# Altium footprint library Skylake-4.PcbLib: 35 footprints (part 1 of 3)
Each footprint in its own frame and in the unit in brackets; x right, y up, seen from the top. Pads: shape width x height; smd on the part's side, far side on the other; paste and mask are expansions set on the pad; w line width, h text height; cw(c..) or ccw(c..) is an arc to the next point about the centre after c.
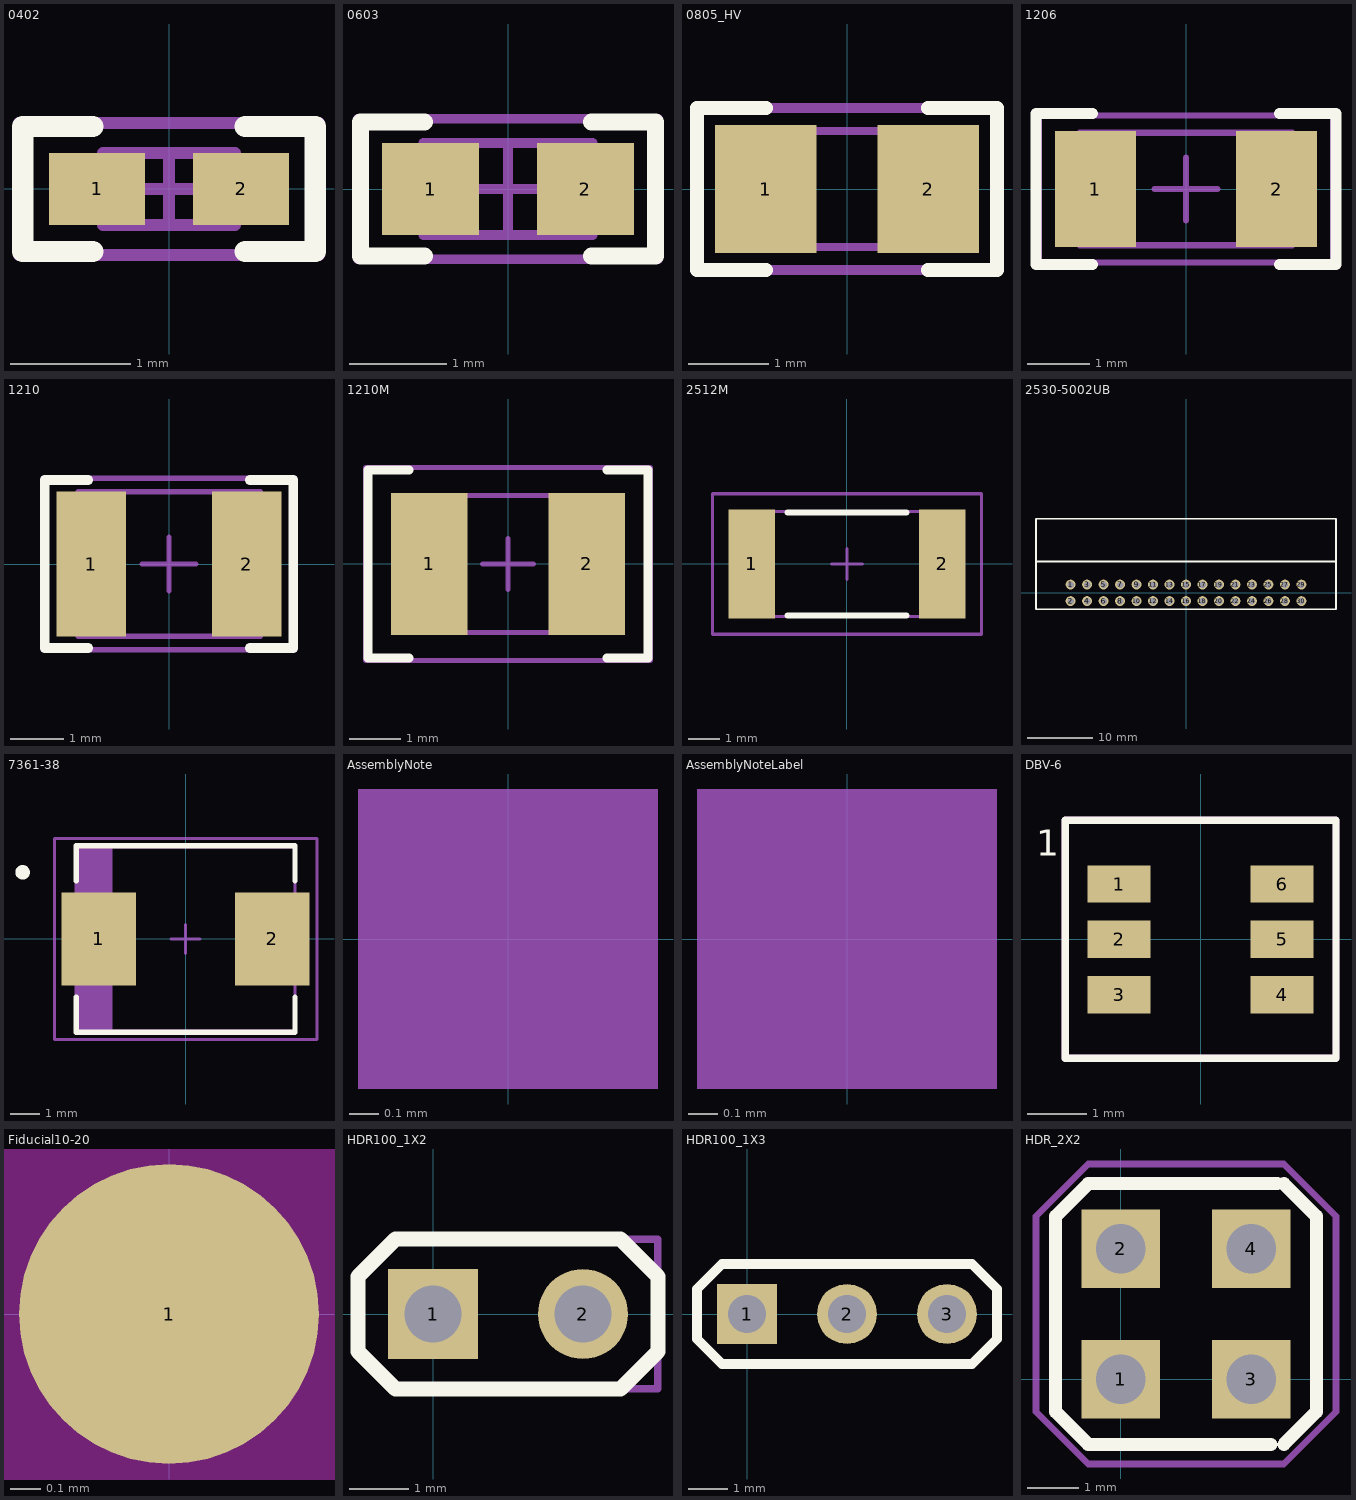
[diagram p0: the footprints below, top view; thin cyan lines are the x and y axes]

## 0402 [mm] "0402 from SM-752 data"
height 0.6
pads (2):
  rect 0.8x0.6 smd: 1(-0.6,0) 2(0.6,0)
Top Overlay:
  lines w0.178: -0.635,-0.521 -1.219,-0.521 -1.219,0.521 -0.635,0.521 ; 0.635,-0.521 1.219,-0.521 1.219,0.521 0.635,0.521
Mechanical 5:
  lines w0.1: -1.25,-0.55 -1.25,0.55 1.25,0.55 1.25,-0.55 -1.25,-0.55
  text ".Designator" at 0.585,0.274 h0.76
Mechanical 13:
  lines w0.1: -0.35,-0.3 -0.35,0.3 ; 0.35,-0.3 0.35,0.3 ; -0.55,-0.3 0.55,-0.3 0.55,0.3 -0.55,0.3 -0.55,-0.3
Mechanical 15:
  lines w0.1: -0.3,0 0.3,0 ; 0,-0.3 0,0.3 ; -1.25,-0.55 1.25,-0.55 1.25,0.55 -1.25,0.55 -1.25,-0.55
3D body: height 0.6, standoff 0, extent 0.351,-0.299 0.549,0.299
3D body: height 0.6, standoff 0, extent -0.349,-0.299 0.349,0.299
3D body: height 0.6, standoff 0, extent -0.549,-0.299 -0.351,0.299

## 0603 [mm] "0603 from SM-752 data"
height 0.85
pads (2):
  rect 1x0.95 smd: 1(-0.8,0) 2(0.8,0)
Top Overlay:
  lines w0.178: -0.864,-0.691 -1.524,-0.691 -1.524,0.693 -0.864,0.693 ; 0.864,-0.691 1.524,-0.691 1.524,0.693 0.864,0.693
Mechanical 5:
  lines w0.1: -1.55,-0.725 -1.55,0.725 1.55,0.725 1.55,-0.725 -1.55,-0.725
  text ".Designator" at -0.583,-0.298 h0.76
Mechanical 13:
  lines w0.1: -0.55,-0.475 -0.55,0.475 ; 0.55,-0.475 0.55,0.475 ; -0.875,-0.475 0.875,-0.475 0.875,0.475 -0.875,0.475 -0.875,-0.475
Mechanical 15:
  lines w0.1: -0.475,0 0.475,0 ; 0,-0.475 0,0.475 ; -1.55,-0.725 1.55,-0.725 1.55,0.725 -1.55,0.725 -1.55,-0.725
3D body: height 0.85, standoff 0, extent -0.874,-0.474 -0.551,0.474
3D body: height 0.85, standoff 0, extent -0.549,-0.474 0.549,0.474
3D body: height 0.85, standoff 0, extent 0.551,-0.474 0.874,0.474

## 0805_HV [mil] "0805 with 30mil clearance between pads"
height 43.31
pads (2):
  rect 50x63 smd: 1(-40,0) 2(40,0)
Top Overlay:
  lines w7: -40,-40 -74,-40 -74,0 -74,40 -40,40 ; 40,-40 74,-40 74,0 74,40 40,40
Mechanical 5:
  lines w5: -74,-40 -74,40 74,40 74,-40 -74,-40
  text ".Designator" at -21.12,-11.04 h30
Mechanical 13:
  lines w3.94: -25.59,-28.54 -25.59,28.54 ; 25.59,-28.54 25.59,28.54 ; -43.31,-28.54 43.31,-28.54 43.31,28.54 -43.31,28.54 -43.31,-28.54
3D body: height 43.31, standoff 0, extent -43.29,-28.52 -25.61,28.52
3D body: height 43.31, standoff 0, extent -25.57,-28.52 25.57,28.52
3D body: height 43.31, standoff 0, extent 25.61,-28.52 43.29,28.52

## 1206 [mm] "1206 from SM-752 data"
height 1.35
pads (2):
  rect 1.3x1.85 smd: 1(-1.45,0) 2(1.45,0)
Top Overlay:
  lines w0.178: -1.5,-1.21 -2.4,-1.21 -2.4,1.21 -1.5,1.21 ; 1.5,-1.21 2.4,-1.21 2.4,1.21 1.5,1.21
Mechanical 5:
  lines w0.1: -1.7,-0.9 -1.7,0.9 1.7,0.9 1.7,-0.9 -1.7,-0.9
  text ".Designator" at 0.404,0.15 h0.81
Mechanical 13:
  lines w0.1: -1.2,-0.9 -1.2,0.9 ; 1.2,-0.9 1.2,0.9 ; -1.7,-0.9 -1.7,0.9 1.7,0.9 1.7,-0.9 -1.7,-0.9
Mechanical 15:
  lines w0.1: -0.5,0 0.5,0 ; 0,-0.5 0,0.5 ; -2.35,-1.175 -2.35,1.175 2.35,1.175 2.35,-1.175 -2.35,-1.175
3D body: height 1.35, standoff 0, extent 1.201,-0.899 1.699,0.899
3D body: height 1.35, standoff 0, extent -1.199,-0.899 1.199,0.899
3D body: height 1.35, standoff 0, extent -1.699,-0.899 -1.201,0.899

## 1210 [mm] "1210 from SM-752 data"
height 1.35
pads (2):
  rect 1.3x2.7 smd: 1(-1.45,0) 2(1.45,0)
Top Overlay:
  lines w0.178: -1.511,-1.568 -2.316,-1.568 -2.316,1.568 -1.511,1.568 ; 1.511,-1.568 2.316,-1.568 2.316,1.568 1.511,1.568
Mechanical 5:
  lines w0.1: -1.7,-1.35 1.7,-1.35 1.7,1.35 -1.7,1.35 -1.7,-1.35
  text ".Designator" at 0.307,0.066 h0.76
Mechanical 13:
  lines w0.1: -1.2,-1.35 -1.2,1.35 ; 1.2,-1.35 1.2,1.35 ; -1.7,-1.35 -1.7,1.35 1.7,1.35 1.7,-1.35 -1.7,-1.35
Mechanical 15:
  lines w0.1: -0.5,0 0.5,0 ; 0,-0.5 0,0.5 ; -2.35,-1.6 -2.35,1.6 2.35,1.6 2.35,-1.6 -2.35,-1.6
3D body: height 1.35, standoff 0, extent -1.699,-1.349 -1.201,1.349
3D body: height 1.35, standoff 0, extent -1.199,-1.349 1.199,1.349
3D body: height 1.35, standoff 0, extent 1.201,-1.349 1.699,1.349

## 1210M [mm] "1210 from SM-752 data"
height 1.35
pads (2):
  rect 1.5x2.8 smd: 1(-1.55,0) 2(1.55,0)
Top Overlay:
  lines w0.178: -1.95,-1.85 -2.75,-1.85 -2.75,1.85 -1.95,1.85 ; 1.95,-1.85 2.75,-1.85 2.75,1.85 1.95,1.85
Mechanical 5:
  lines w0.1: -1.7,-1.35 -1.7,1.35 1.7,1.35 1.7,-1.35 -1.7,-1.35
  text ".Designator" at 0.58,0.169 h0.76
Mechanical 13:
  lines w0.1: -1.2,-1.35 -1.2,1.35 ; 1.2,-1.35 1.2,1.35 ; -1.7,-1.35 1.7,-1.35 1.7,1.35 -1.7,1.35 -1.7,-1.35
Mechanical 15:
  lines w0.1: -0.5,0 0.5,0 ; 0,-0.5 0,0.5 ; -2.8,-1.9 -2.8,1.9 2.8,1.9 2.8,-1.9 -2.8,-1.9
3D body: height 1.35, standoff 0, extent 1.201,-1.349 1.699,1.349
3D body: height 1.35, standoff 0, extent -1.199,-1.349 1.199,1.349
3D body: height 1.35, standoff 0, extent -1.699,-1.349 -1.201,1.349

## 2512M [mm] "Chip Resistor, Body 6.3x3.2mm, IPC Low Density"
height 0.71
pads (2):
  rect 1.5x3.5 smd: 1(-3.05,0) 2(3.05,0)
Top Overlay:
  lines w0.2: -1.9,-1.65 1.9,-1.65 ; -1.9,1.65 1.9,1.65
Mechanical 5:
  lines w0.1: -3.225,-1.675 3.225,-1.675 3.225,1.675 -3.225,1.675 -3.225,-1.675
  text ".Designator" at -0.051,0.064 h0.76
Mechanical 13:
  lines w0.1: -2.463,-1.675 -2.463,1.675 ; 2.463,-1.675 2.463,1.675 ; -3.225,-1.675 3.225,-1.675 3.225,1.675 -3.225,1.675 -3.225,-1.675
Mechanical 15:
  lines w0.1: -0.5,0 0.5,0 ; 0,-0.5 0,0.5 ; -4.3,-2.25 4.3,-2.25 4.3,2.25 -4.3,2.25 -4.3,-2.25
3D body: height 0.71, standoff 0, extent -3.224,-1.674 -2.464,1.674
3D body: height 0.71, standoff 0, extent -2.462,-1.674 2.462,1.674
3D body: height 0.71, standoff 0, extent 2.464,-1.674 3.224,1.674

## 2530-5002UB [mil]
height 340
pads (30):
  round 60 hole 40: 1(-700,50) 2(-700,-50) 3(-600,50) 4(-600,-50) 5(-500,50) 6(-500,-50) 7(-400,50) 8(-400,-50) 9(-300,50) 10(-300,-50) 11(-200,50) 12(-200,-50) 13(-100,50) 14(-100,-50) 15(0,50) 16(0,-50) 17(100,50) 18(100,-50) 19(200,50) 20(200,-50) 21(300,50) 22(300,-50) 23(400,50) 24(400,-50) 25(500,50) 26(500,-50) 27(600,50) 28(600,-50) 29(700,50) 30(700,-50)
Top Overlay:
  lines w10: -910,190 910,190 ; -910,-100 910,-100 910,450 -910,450 -910,-100

## 7361-38 [mm] "Medium density IPC based on AVX dimensions for TPS series"
height 3.75
pads (2):
  rect 2.55x3.2 smd: 1(-2.975,0) 2(2.975,0)
Top Overlay:
  circle w0.25: c-5.586,2.286 r0.125
  lines w0.178: -3.75,-1.989 -3.75,-3.2 3.75,-3.2 3.75,-1.989 ; -3.75,1.989 -3.75,3.2 3.75,3.2 3.75,1.989
Mechanical 5:
  rectangle: -3.75,-3.15 -2.55,3.15
  lines w0.1: -2.55,-3.15 -2.55,3.15 ; -3.75,-3.15 3.75,-3.15 3.75,3.15 -3.75,3.15 -3.75,-3.15
  text ".Designator" at 0.772,0.036 h0.76
Mechanical 15:
  lines w0.1: -0.5,0 0.5,0 ; 0,-0.5 0,0.5 ; -4.5,-3.45 -4.5,3.45 4.5,3.45 4.5,-3.45 -4.5,-3.45
3D body: height 3.8, standoff 0, extent -3.75,-3.15 3.75,3.15
3D body: height 3.8, standoff 3.8, extent -3.749,-3.149 -2.551,3.149

## AssemblyNote [mm] "Assembly Note"
Mechanical 5:
  rectangle: -0.508,-0.508 0.508,0.508
  text ".Designator" at -4.191,-0.508 h0.76
  text ".Comment" at 1.143,-0.508 h0.76

## AssemblyNoteLabel [mm] "Assembly Note for PCB Labels"
Mechanical 5:
  rectangle: -0.508,-0.508 0.508,0.508
  text ".Designator" at -4.191,-0.508 h0.76
  text "Install label in silkscreened box after final wash.  Text shall be 8 pt font.  Text shall be per the Label Table in the PDF schematic." at 1.143,-0.508 h0.76

## DBV-6 [mil]
height 33.46
pads (6):
  rect 42x25 smd: 1(-54.5,37) 2(-54.5,0) 3(-54.5,-37) 4(54.5,-37) 5(54.5,0) 6(54.5,37)
Top Overlay:
  lines w5: -90.5,-79.5 90.5,-79.5 90.5,79.5 -90.5,79.5 -90.5,-79.5
  text "1" at -110,50 h30
Mechanical 5:
  lines w5: -90.5,-79.5 -90.5,79.5 90.5,79.5 90.5,-79.5 -90.5,-79.5
  text ".Designator" at 12,2.18 h30
  text "*" at -65,40 h25

## Fiducial10-20 [mm]
pads (1):
  round 1 smd paste-0.5 mask+0.5: 1(0,0)
Top Layer keep-out:
  circle w1.178: c0,0 r0.5

## HDR100_1X2 [mil]
height 102.1
pads (2):
  rect 60x60 hole 38: 1(0,0)
  round 60 hole 38: 2(100,0)
Top Overlay:
  lines w10: -50,-25 -50,25 -25,50 125,50 150,25 150,-25 125,-50 -25,-50 -50,-25
Mechanical 5:
  lines w5: -50,-25 -25,-50 150,-50 150,50 -25,50 -50,25 -50,-25
  text ".Designator" at 84.4,13.65 h30

## HDR100_1X3 [mil]
height 102.1
pads (3):
  rect 60x60 hole 38: 1(0,0)
  round 60 hole 38: 2(100,0) 3(200,0)
Top Overlay:
  lines w10: -50,-25 -25,-50 225,-50 250,-25 250,25 225,50 -25,50 -50,25 -50,-25
Mechanical 5:
  lines w5: -50,-25 -25,-50 225,-50 250,-25 250,25 225,50 -25,50 -50,25 -50,-25
  text ".Designator" at 105.47,-18.86 h30

## HDR_2X2 [mil]
height 102.1
pads (4):
  rect 60x60 hole 38: 1(0,0) 2(0,100) 3(100,0) 4(100,100)
Top Overlay:
  lines w10: 115,-50 -25,-50 -50,-25 -50,125 -25,150 120,150 ; 125,-50 150,-25 150,125 125,150
Mechanical 5:
  lines w5: -65,-25 -25,-65 125,-65 165,-25 165,125 125,165 -25,165 -65,125 -65,-25
  text ".Designator" at 30.4,54.41 h30
  text "*" at -19,-56 h30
